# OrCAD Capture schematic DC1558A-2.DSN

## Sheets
1 Sequencer: size Custom; title: 8 - OUTPUT REGULATOR WITH SEQUENCING AND I   C; rev: 2; note: DEMO CIRCUIT 1558A
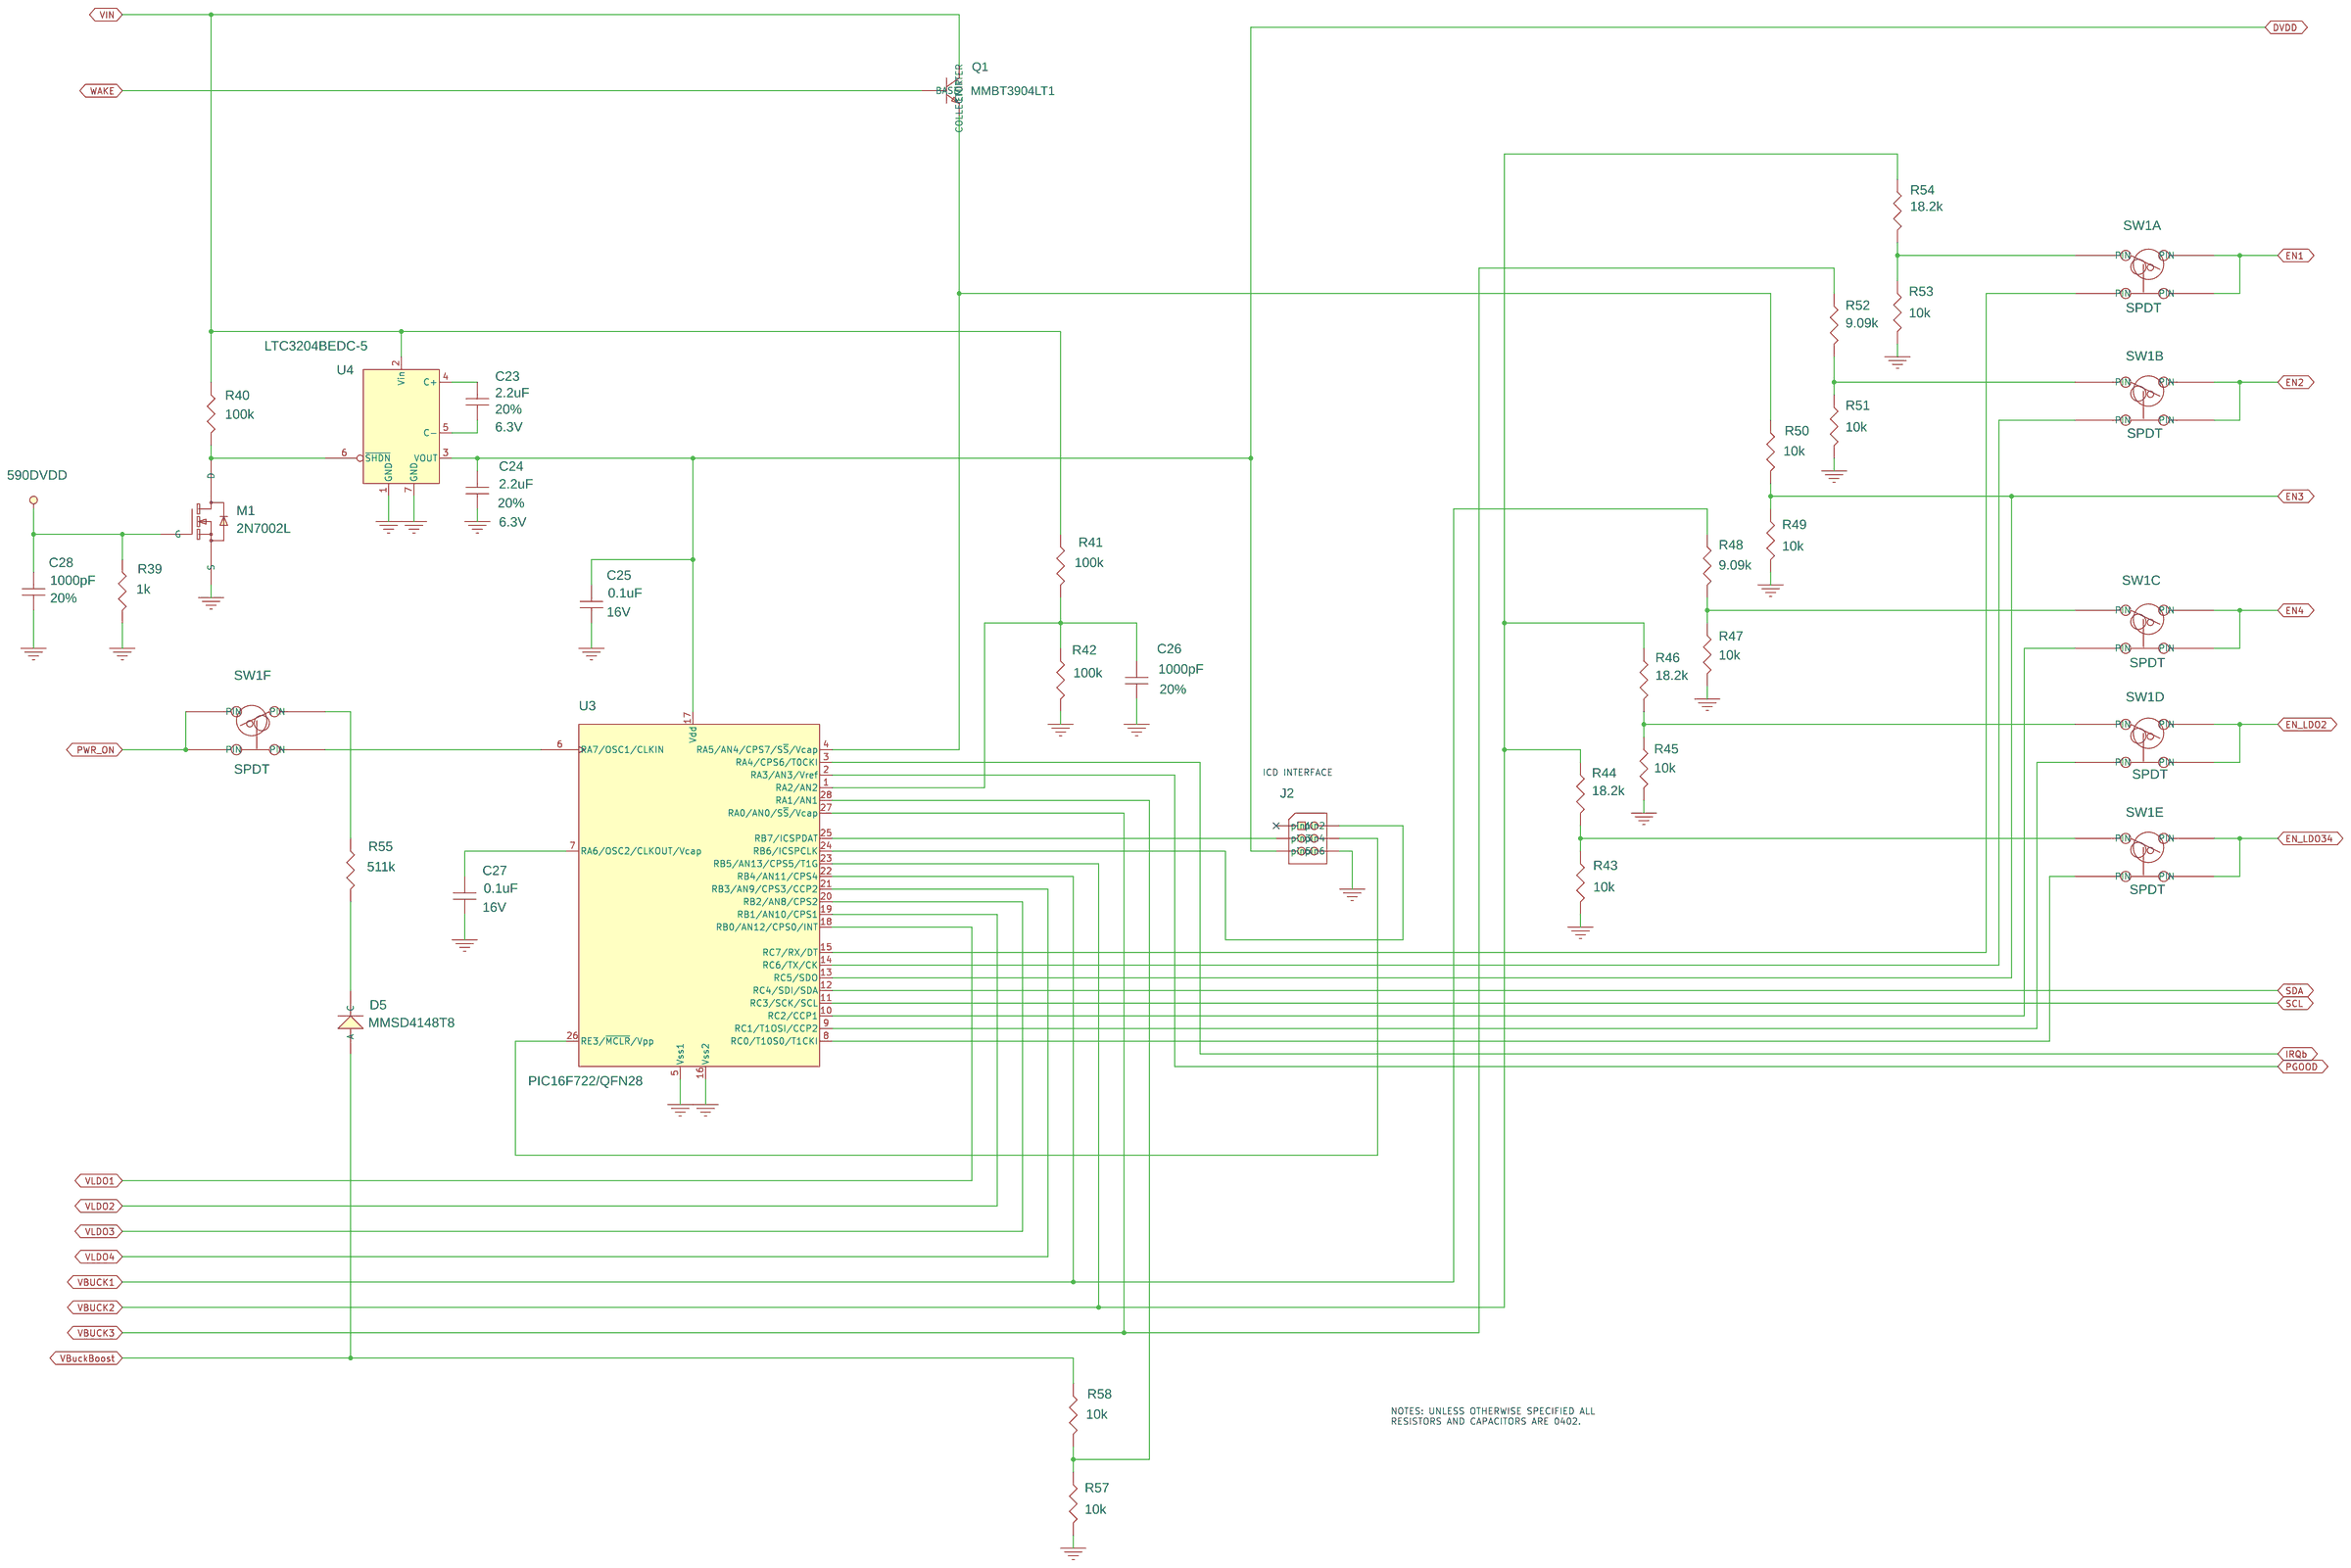
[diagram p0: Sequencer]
2 LTC3589EUJ: size Custom
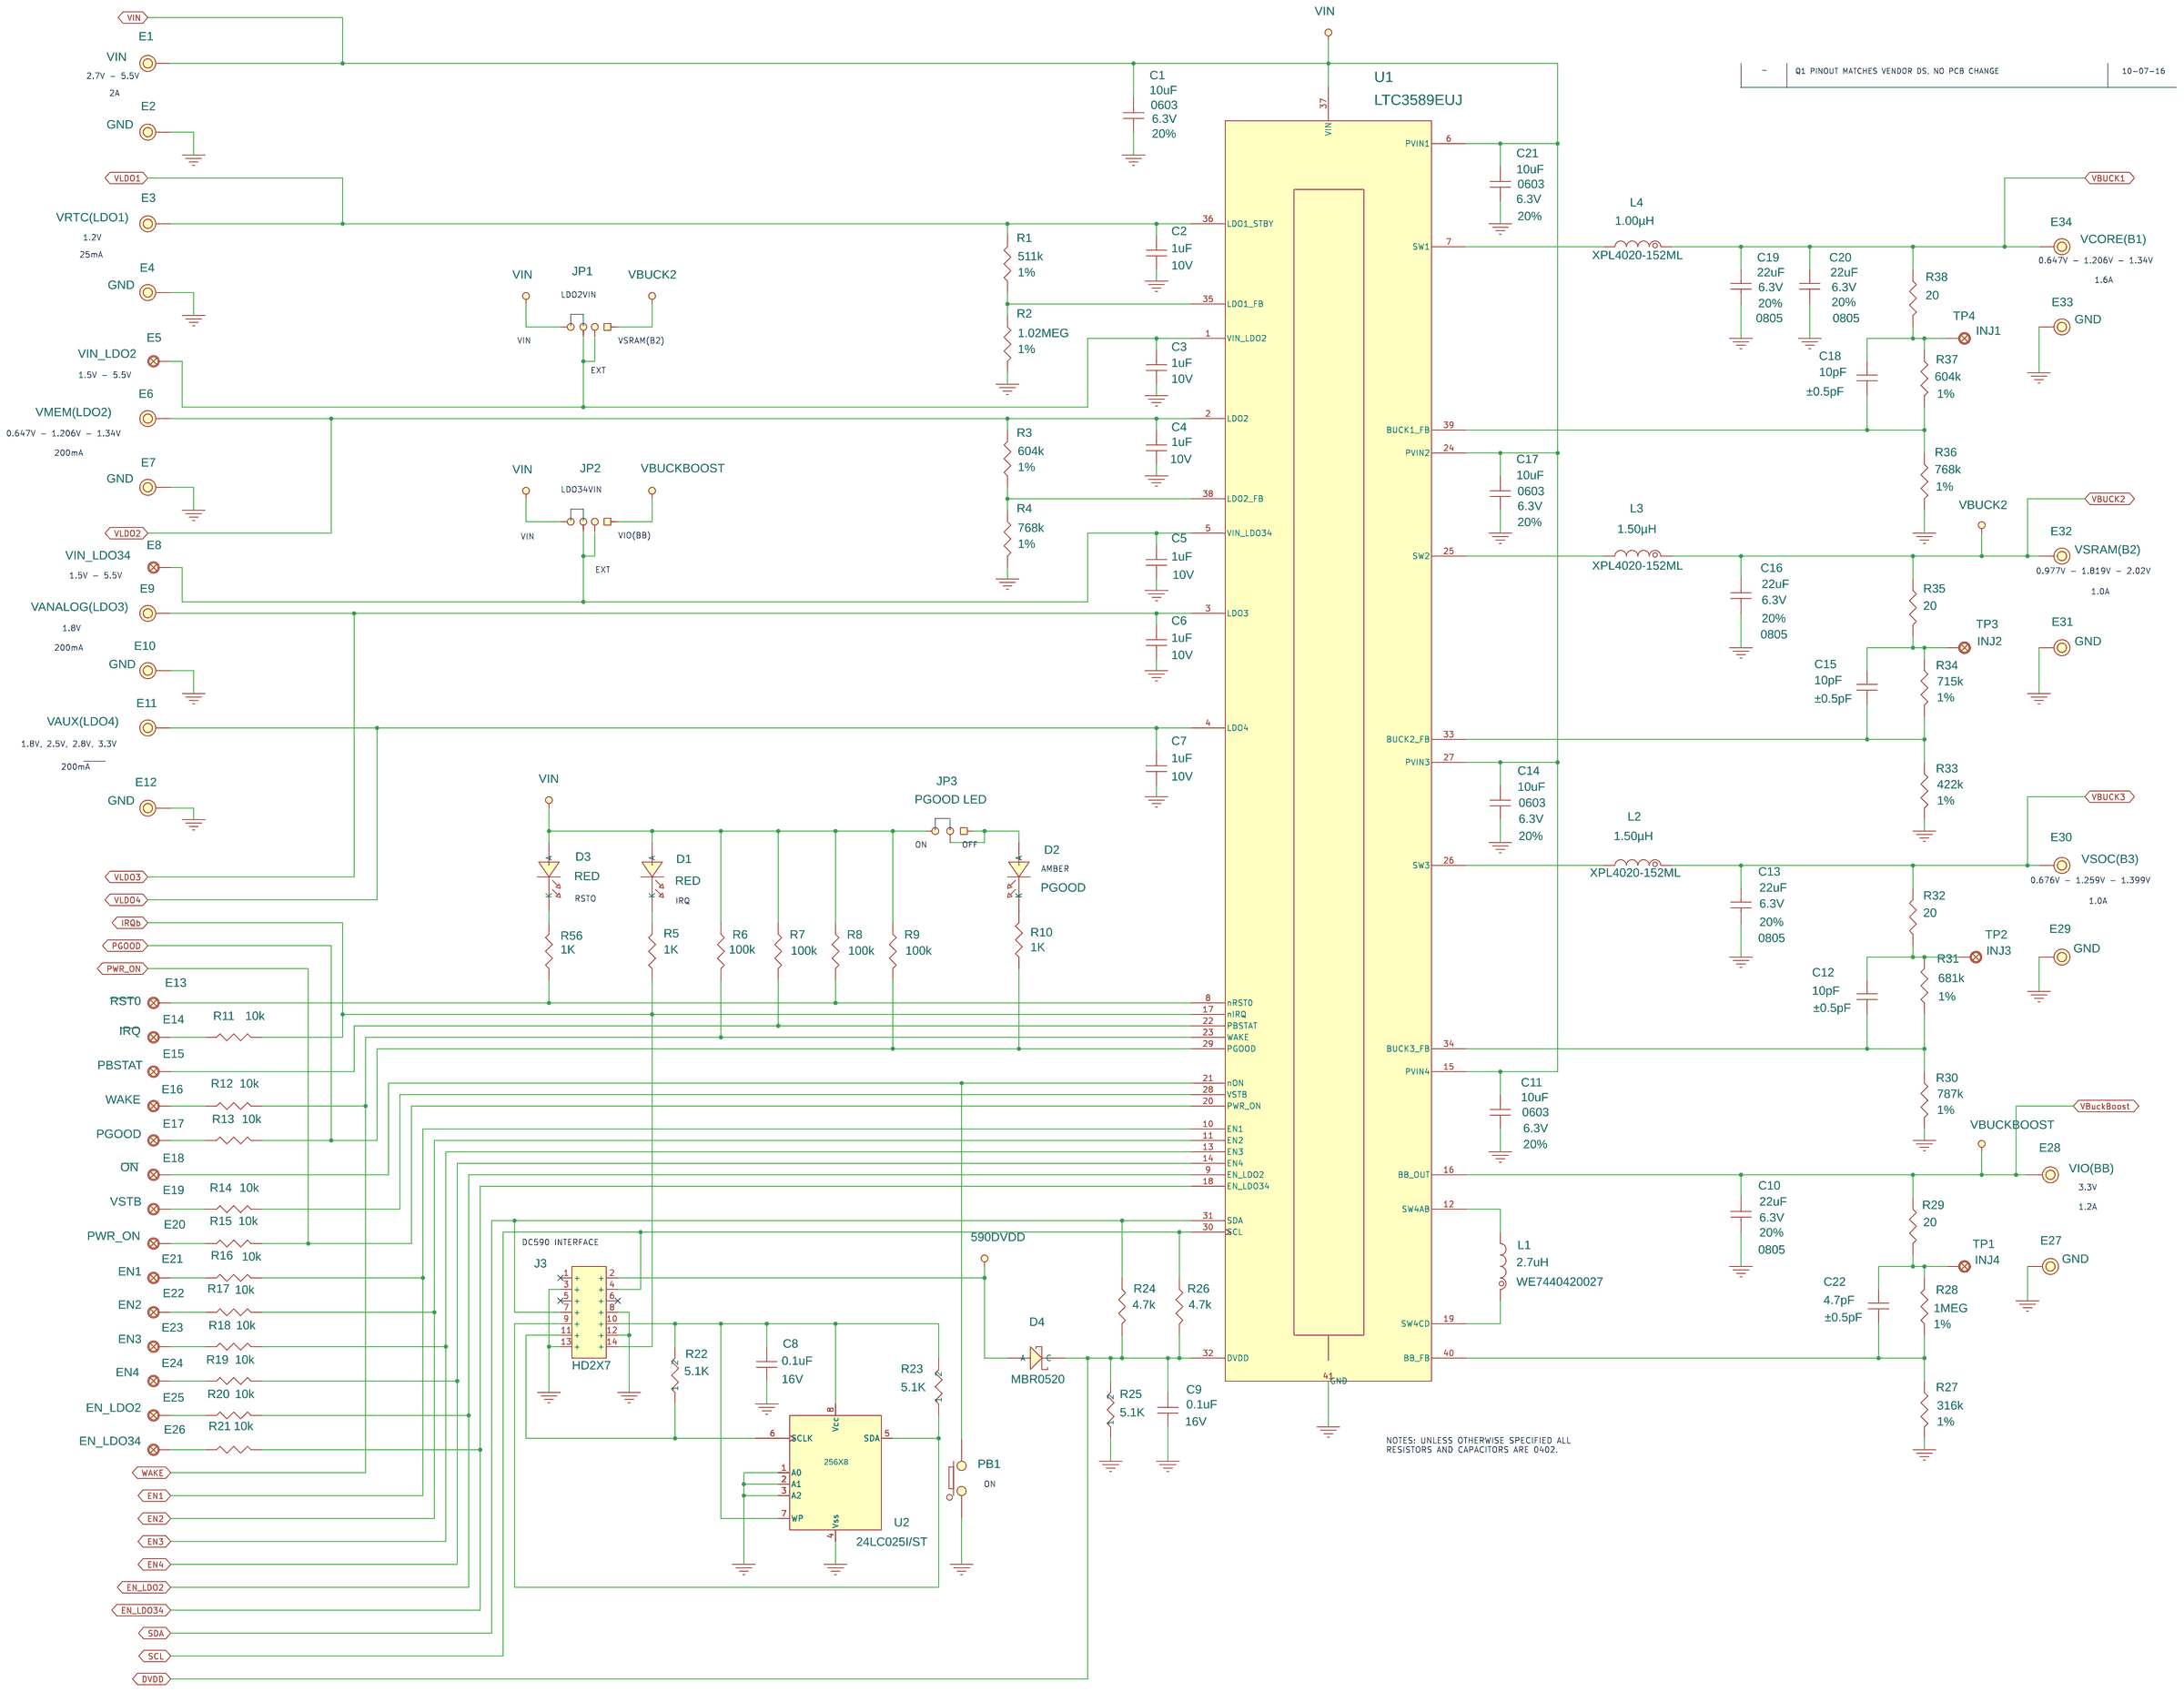
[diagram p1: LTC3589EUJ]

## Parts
sheet LTC3589EUJ
C1  10uF  [CC0603SMALL]
C2  1uF  [0402-SMALL]
C3  1uF  [0402-SMALL]
C4  1uF  [0402-SMALL]
C5  1uF  [0402-SMALL]
C6  1uF  [0402-SMALL]
C7  1uF  [0402-SMALL]
C8  0.1uF  [0402-SMALL]
C9  0.1uF  [0402-SMALL]
C10  22uF  [0805]
C11  10uF  [CC0603SMALL]
C12  10pF  [0402-SMALL]
C13  22uF  [0805]
C14  10uF  [CC0603SMALL]
C15  10pF  [0402-SMALL]
C16  22uF  [0805]
C17  10uF  [CC0603SMALL]
C18  10pF  [0402-SMALL]
C19  22uF  [0805]
C20  22uF  [0805]
C21  10uF  [CC0603SMALL]
C22  4.7pF  [0402-SMALL]
D1  RED  [LNJ208R8ARA-RED-LED]
D2  PGOOD  [LITE-ON-GREEN-LED]
D3  RED  [LNJ208R8ARA-RED-LED]
D4  MBR0520  [SOD-123]
E1  0.09"  [MILL-MAX-2501-2]
E2  0.09"  [MILL-MAX-2501-2]
E3  0.09"  [MILL-MAX-2501-2]
E4  0.09"  [MILL-MAX-2501-2]
E5  0.061"  [MILL-MAX-2308]
E6  0.09"  [MILL-MAX-2501-2]
E7  0.09"  [MILL-MAX-2501-2]
E8  0.061"  [MILL-MAX-2308]
E9  0.09"  [MILL-MAX-2501-2]
E10  0.09"  [MILL-MAX-2501-2]
E11  0.09"  [MILL-MAX-2501-2]
E12  0.09"  [MILL-MAX-2501-2]
E13  0.061"  [MILL-MAX-2308]
E14  0.061"  [MILL-MAX-2308]
E15  0.061"  [MILL-MAX-2308]
E16  0.061"  [MILL-MAX-2308]
E17  0.061"  [MILL-MAX-2308]
E18  0.061"  [MILL-MAX-2308]
E19  0.061"  [MILL-MAX-2308]
E20  0.061"  [MILL-MAX-2308]
E21  0.061"  [MILL-MAX-2308]
E22  0.061"  [MILL-MAX-2308]
E23  0.061"  [MILL-MAX-2308]
E24  0.061"  [MILL-MAX-2308]
E25  0.061"  [MILL-MAX-2308]
E26  0.061"  [MILL-MAX-2308]
E27  0.09"  [MILL-MAX-2501-2]
E28  0.09"  [MILL-MAX-2501-2]
E29  0.09"  [MILL-MAX-2501-2]
E30  0.09"  [MILL-MAX-2501-2]
E31  0.09"  [MILL-MAX-2501-2]
E32  0.09"  [MILL-MAX-2501-2]
E33  0.09"  [MILL-MAX-2501-2]
E34  0.09"  [MILL-MAX-2501-2]
J3  HD2X7  [HD2X7-079-MOLEX]
JP1  4 pin jumper  [2MMJUMP4]
JP2  4 pin jumper  [2MMJUMP4]
JP3  PGOOD LED  [2MMJUMP3]
L1  2.7uH  [IND-WE-7440420027]
L2  1.50µH  [IND-XPL4020]
L3  1.50µH  [IND-XPL4020]
L4  1.00µH  [IND-XPL4020]
PB1  EVQPPFA25  [SW-EVQPJS]
R1  511k  [0402-SMALL]
R2  1.02MEG  [0402-SMALL]
R3  604k  [0402-SMALL]
R4  768k  [0402-SMALL]
R5  1K  [0402-SMALL]
R6  100k  [0402-SMALL]
R7  100k  [0402-SMALL]
R8  100k  [0402-SMALL]
R9  100k  [0402-SMALL]
R10  1K  [0402-SMALL]
R11  10k  [0402-SMALL]
R12  10k  [0402-SMALL]
R13  10k  [0402-SMALL]
R14  10k  [0402-SMALL]
R15  10k  [0402-SMALL]
R16  10k  [0402-SMALL]
R17  10k  [0402-SMALL]
R18  10k  [0402-SMALL]
R19  10k  [0402-SMALL]
R20  10k  [0402-SMALL]
R21  10k  [0402-SMALL]
R22  5.1K  [0402-SMALL]
R23  5.1K  [0402-SMALL]
R24  4.7k  [0402-SMALL]
R25  5.1K  [0402-SMALL]
R26  4.7k  [0402-SMALL]
R27  316k  [0402-SMALL]
R28  1MEG  [0402-SMALL]
R29  20  [0402-SMALL]
R30  787k  [0402-SMALL]
R31  681k  [0402-SMALL]
R32  20  [0402-SMALL]
R33  422k  [0402-SMALL]
R34  715k  [0402-SMALL]
R35  20  [0402-SMALL]
R36  768k  [0402-SMALL]
R37  604k  [0402-SMALL]
R38  20  [0402-SMALL]
R56  1K  [0402-SMALL]
TP1  0.030"  [PAD70-70]
TP2  0.030"  [PAD70-70]
TP3  0.030"  [PAD70-70]
TP4  0.030"  [PAD70-70]
U1  LTC3589  [QFN(40)(UJ)6MMX6MM.5]
U2  24LC025I/ST  [TSSOP8]
sheet Sequencer
C23  2.2uF  [0402-SMALL]
C24  2.2uF  [0402-SMALL]
C25  0.1uF  [0402-SMALL]
C26  1000pF  [0402-SMALL]
C27  0.1uF  [0402-SMALL]
C28  1000pF  [0402-SMALL]
D5  MMSD4148T8  [SOD-123]
J2  TMM-103-02-L-D  [JP2X3/079]
M1  2N7002L  [SUPER_SOT3]
Q1  MMBT3904LT1  [MMBT3904-SOT-23]
R39  1k  [0402-SMALL]
R40  100k  [0402-SMALL]
R41  100k  [0402-SMALL]
R42  100k  [0402-SMALL]
R43  10k  [0402-SMALL]
R44  18.2k  [0402-SMALL]
R45  10k  [0402-SMALL]
R46  18.2k  [0402-SMALL]
R47  10k  [0402-SMALL]
R48  9.09k  [0402-SMALL]
R49  10k  [0402-SMALL]
R50  10k  [0402-SMALL]
R51  10k  [0402-SMALL]
R52  9.09k  [0402-SMALL]
R53  10k  [0402-SMALL]
R54  18.2k  [0402-SMALL]
R55  511k  [0402-SMALL]
R57  10k  [0402-SMALL]
R58  10k  [0402-SMALL]
SW1  SPDT  [SPDT-204-126]  (sections A,B,C,D,E,F)
U3  PIC16F722/QFN28  [6mmx6mmQFN28]
U4  LTC3204BEDC-5  [DFN(06)2MMX2MM]

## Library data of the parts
C1 C11 C14 C17 C21 = C1608X5R0J475M: 1st Part Field: 6.3V; 2nd Part Field: 0603; 3rd Part Field: CHIP,; 4th Part Field: MUR; 5th Part Field: C1608X5R0J106M; 7th Part Field: CAP, X5R; Critical: T; Layer: T; MPN: C1608X5R0J106M; Manufacturer: TDK; Populate: T; Size: 0603; Tempco: X5R; Tolerance: 20%; Voltage: 6.3V
C2-C7 = C2012X5R0J156M: 1st Part Field: 10V; 2nd Part Field: 0402; 3rd Part Field: CHIP, X5R; 5th Part Field: C1005X5R1A105K; 7th Part Field: CAP,; Critical: T; Layer: T; MPN: C1005X5R0J105KT; Manufacturer: TDK; Part Number: TDK, 1005X5R0J105M; Populate: T; Size: 0402; Tempco: X5R; Tolerance: 10%; Voltage: 10V
C8 C9 = C1608X5R0J475M: 1st Part Field: 16V; 2nd Part Field: 0402; 3rd Part Field: CHIP, X5R; 4th Part Field: MUR; 5th Part Field: GRM188R60J106ME47; 7th Part Field: CAP, X5R; Critical: T; Layer: T; MPN: GRM155R71C104KA88; Manufacturer: MUR; Populate: T; Size: 0402; Tempco: JIS-B; Tolerance: 10%; Voltage: 16V
C10 C13 C16 C19 C20 = C2012X5R0J156M: 3rd Part Field: CHIP, X5R; 4th Part Field: Taiyo-Yuden; 5th Part Field: JMK212BJ226MG; 7th Part Field: CAP,; Critical: T; Layer: T; MPN: JMK212BJ226MG; Manufacturer: Taiyo-Yuden; Part Number: Taiyo-Yuden, JMK212BJ226MG; Populate: T; Tempco: X5R; Tolerance: 20%; Voltage: 6.3V
C12 C22 = C2012X5R0J156M: 1st Part Field: 50V; 2nd Part Field: 0402; 3rd Part Field: CHIP; 4th Part Field: VISHAY; 5th Part Field: VJ0402A100DXAA; 7th Part Field: CAP,; Critical: T; Layer: T; MPN: 04025A100KAT; Manufacturer: AVX; Part Number: AVX, 04015A100KAT; Populate: T; Size: 0402; Tempco: C0G; Tolerance: ±0.5pF; Voltage: 50V
C15 C18 = C2012X5R0J156M: 1st Part Field: 50V; 2nd Part Field: 0402; 3rd Part Field: CHIP; 4th Part Field: VISHAY; 5th Part Field: VJ0402A100DXAA; 7th Part Field: CAP,; Critical: T; Layer: T; MPN: VJ0402A100DXAA; Manufacturer: VISHAY; Part Number: VISHAY, VJ0402A100DXAA; Populate: T; Size: 0402; Tempco: C0G; Tolerance: ±0.5pF; Voltage: 50V
D1 D3 = ln1351-c-tr_1: 5th Part Field: LNJ208R8ARA; 9th Part Field: SMT, GREEN; Critical: F; Irms: 1mA; Layer: T; MPN: LNJ208R8ARA; Manufacturer: PANASONIC; Part Number: LNJ208R8ARA; Populate: T; Size: 0603
D2 = ln1351-c-tr_1: 5th Part Field: LNJ336W83RA; 9th Part Field: SMT, GREEN; Part Number: LNJ336W83RA
D4 = DIODE_SCHOTTKY
E1 = E_3: TURRET; Critical: F; MPN: 2501-2; Manufacturer: MIL; Populate: T; Signal: VIN; Size: 0.09
E2 E4 E7 E10 E12 E27 E29 E31 E33 = E_3: TURRET; Critical: F; MPN: 2501-2; Manufacturer: MIL; Populate: T; Signal: GND; Size: 0.09
E3 = E_3: TURRET; Critical: F; MPN: 2501-2; Manufacturer: MIL; Populate: T; Signal: VRTC(LDO1); Size: 0.09
E5 = TP_KEY_1502-2_0: 4th Part Field: MILL-MAX; 5th Part Field: 2308-2; 7th Part Field: TURRET, SIGNAL; 9th Part Field: NTC; Critical: F; MPN: 2308-2; Manufacturer: MIL; Part Number: MILL-MAX 2308-2; Populate: T; Signal: VIN_LDO2; Size: 0.061
E6 = E_3: TURRET; Critical: F; MPN: 2501-2; Manufacturer: MIL; Populate: T; Signal: VMEM(LDO2); Size: 0.09
E8 = TP_KEY_1502-2_0: 4th Part Field: MILL-MAX; 5th Part Field: 2308-2; 7th Part Field: TURRET, SIGNAL; 9th Part Field: NTC; Critical: F; MPN: 2308-2; Manufacturer: MIL; Part Number: MILL-MAX 2308-2; Populate: T; Signal: VIN_LDO34; Size: 0.061
E9 = E_3: TURRET; Critical: F; MPN: 2501-2; Manufacturer: MIL; Populate: T; Signal: VANALOG(LDO3); Size: 0.09
E11 = E_3: TURRET; Critical: F; MPN: 2501-2; Manufacturer: MIL; Populate: T; Signal: VAUX(LDO4); Size: 0.09
E13 = TP_KEY_1502-2_0: 4th Part Field: MILL-MAX; 5th Part Field: 2308-2; 7th Part Field: TURRET, SIGNAL; 9th Part Field: NTC; Critical: F; MPN: 2308-2; Manufacturer: MIL; Part Number: MILL-MAX 2308-2; Populate: T; Signal: RST0; Size: 0.061
E14 = TP_KEY_1502-2_0: 4th Part Field: MILL-MAX; 5th Part Field: 2308-2; 7th Part Field: TURRET, SIGNAL; 9th Part Field: NTC; Critical: F; MPN: 2308-2; Manufacturer: MIL; Part Number: MILL-MAX 2308-2; Populate: T; Signal: IRQ; Size: 0.061
E15 = TP_KEY_1502-2_0: 4th Part Field: MILL-MAX; 5th Part Field: 2308-2; 7th Part Field: TURRET, SIGNAL; 9th Part Field: NTC; Critical: F; MPN: 2308-2; Manufacturer: MIL; Part Number: MILL-MAX 2308-2; Populate: T; Signal: PBSTAT; Size: 0.061
E16 = TP_KEY_1502-2_0: 4th Part Field: MILL-MAX; 5th Part Field: 2308-2; 7th Part Field: TURRET, SIGNAL; 9th Part Field: NTC; Critical: F; MPN: 2308-2; Manufacturer: MIL; Part Number: MILL-MAX 2308-2; Populate: T; Signal: WAKE; Size: 0.061
E17 = TP_KEY_1502-2_0: 4th Part Field: MILL-MAX; 5th Part Field: 2308-2; 7th Part Field: TURRET, SIGNAL; 9th Part Field: NTC; Critical: F; MPN: 2308-2; Manufacturer: MIL; Part Number: MILL-MAX 2308-2; Populate: T; Signal: PGOOD; Size: 0.061
E18 = TP_KEY_1502-2_0: 4th Part Field: MILL-MAX; 5th Part Field: 2308-2; 7th Part Field: TURRET, SIGNAL; 9th Part Field: NTC; Critical: F; MPN: 2308-2; Manufacturer: MIL; Part Number: MILL-MAX 2308-2; Populate: T; Signal: ON; Size: 0.061
E19 = TP_KEY_1502-2_0: 4th Part Field: MILL-MAX; 5th Part Field: 2308-2; 7th Part Field: TURRET, SIGNAL; 9th Part Field: NTC; Critical: F; MPN: 2308-2; Manufacturer: MIL; Part Number: MILL-MAX 2308-2; Populate: T; Signal: VSTB; Size: 0.061
E20 = TP_KEY_1502-2_0: 4th Part Field: MILL-MAX; 5th Part Field: 2308-2; 7th Part Field: TURRET, SIGNAL; 9th Part Field: NTC; Critical: F; MPN: 2308-2; Manufacturer: MIL; Part Number: MILL-MAX 2308-2; Populate: T; Signal: PWR_ON; Size: 0.061
E21 = TP_KEY_1502-2_0: 4th Part Field: MILL-MAX; 5th Part Field: 2308-2; 7th Part Field: TURRET, SIGNAL; 9th Part Field: NTC; Critical: F; MPN: 2308-2; Manufacturer: MIL; Part Number: MILL-MAX 2308-2; Populate: T; Signal: EN1; Size: 0.061
E22 = TP_KEY_1502-2_0: 4th Part Field: MILL-MAX; 5th Part Field: 2308-2; 7th Part Field: TURRET, SIGNAL; 9th Part Field: NTC; Critical: F; MPN: 2308-2; Manufacturer: MIL; Part Number: MILL-MAX 2308-2; Populate: T; Signal: EN2; Size: 0.061
E23 = TP_KEY_1502-2_0: 4th Part Field: MILL-MAX; 5th Part Field: 2308-2; 7th Part Field: TURRET, SIGNAL; 9th Part Field: NTC; Critical: F; MPN: 2308-2; Manufacturer: MIL; Part Number: MILL-MAX 2308-2; Populate: T; Signal: EN3; Size: 0.061
E24 = TP_KEY_1502-2_0: 4th Part Field: MILL-MAX; 5th Part Field: 2308-2; 7th Part Field: TURRET, SIGNAL; 9th Part Field: NTC; Critical: F; MPN: 2308-2; Manufacturer: MIL; Part Number: MILL-MAX 2308-2; Populate: T; Signal: EN4; Size: 0.061
E25 = TP_KEY_1502-2_0: 4th Part Field: MILL-MAX; 5th Part Field: 2308-2; 7th Part Field: TURRET, SIGNAL; 9th Part Field: NTC; Critical: F; MPN: 2308-2; Manufacturer: MIL; Part Number: MILL-MAX 2308-2; Populate: T; Signal: EN_LDO2; Size: 0.061
E26 = TP_KEY_1502-2_0: 4th Part Field: MILL-MAX; 5th Part Field: 2308-2; 7th Part Field: TURRET, SIGNAL; 9th Part Field: NTC; Critical: F; MPN: 2308-2; Manufacturer: MIL; Part Number: MILL-MAX 2308-2; Populate: T; Signal: EN_LDO34; Size: 0.061
E28 = E_3: TURRET; Critical: F; MPN: 2501-2; Manufacturer: MIL; Populate: T; Signal: VIO(BB); Size: 0.09
E30 = E_3: TURRET; Critical: F; MPN: 2501-2; Manufacturer: MIL; Populate: T; Signal: VSOC(B3); Size: 0.09
E32 = E_3: TURRET; Critical: F; MPN: 2501-2; Manufacturer: MIL; Populate: T; Signal: VSRAM(B2); Size: 0.09
E34 = E_3: TURRET; Critical: F; MPN: 2501-2; Manufacturer: MIL; Populate: T; Signal: VCORE(B1); Size: 0.09
J3 = CON14AP: 3rd Part Field: 2x7 2MM STRAIGHT; 4th Part Field: MOLEX/WALDEN; 5th Part Field: 87831-1412; 7th Part Field: Socket; Critical: F; MPN: 87831-1420; Manufacturer: MOL; Populate: T; Size: 2X7
JP1 JP2 = 2MMX2MM4PIN_1: Critical: F; MPN: TMM-104-02-L-S; Manufacturer: SAM; Populate: T; Size: 2mm
JP3 = JP3X1_079_NO_6: 4TH PART FIELD: SAMTEC; 5TH PART FIELD: TMM-103-02-L-S; 7TH PART FIELD: HEADER; Part Number: TMM-103-02-L-S
L1 = MSS5131-222MLC: 5th Part Field: WE7440420027
L2 L3 = XPL4020-152MLC_0: PART: XPL4020-152ML
L4 = XPL4020-102MLC: PART: XPL4020-152ML
PB1 = SW-BUTTON_0: 4th Part Field: Panasonic; 7th Part Field: SW MC
R1 = CR16-103JM_0: 1st Part Field: 1/16W; 2nd Part Field: 0402; 3rd Part Field: CHIP; 4th Part Field: VISHAY; 5th Part Field: CRCW0402511KFKED; 7th Part Field: RES,; Critical: T; Layer: T; MPN: CRCW0402511KFKED; Manufacturer: VIS; Part Number: VISHAY CRCW0402 511k 1%; Populate: T; Size: 0402; Tempco: 200PPM; Tolerance: 1%; Voltage: 50V; Wattage: 1/16W
R2 R4 R28 R30 R33 R36 = CR16-103JM_0: 1st Part Field: 1/16W; 2nd Part Field: 0402; 3rd Part Field: CHIP; 4th Part Field: VISHAY; 5th Part Field: CRCW04021M00FKED; 7th Part Field: RES,; Critical: T; Layer: T; MPN: CRCW04021M00FKED; Manufacturer: VIS; Part Number: VISHAY CRCW0402 1MEG 1%; Populate: T; Size: 0402; Tempco: 200PPM; Tolerance: 1%; Voltage: 50V; Wattage: 1/16W
R3 R37 = CR16-103JM_0: 1st Part Field: 1/16W; 2nd Part Field: 0402; 3rd Part Field: CHIP; 4th Part Field: VISHAY; 5th Part Field: CRCW0402787KFKED; 7th Part Field: RES,; Critical: T; Layer: T; MPN: CRCW0402787KFKED; Manufacturer: VIS; Part Number: VISHAY CRCW0402 787k 1%; Populate: T; Size: 0402; Tempco: 200PPM; Tolerance: 1%; Voltage: 50V; Wattage: 1/16W
R5 R56 = CR16-103JM_0: 1st Part Field: 1/16W; 2nd Part Field: 0402; 3rd Part Field: CHIP; 4th Part Field: VISHAY; 5th Part Field: CRCW04021K00JNED; 7th Part Field: RES; Part Number: VISHAY CRCW04021K00JNED; Tolerance: 5%
R6-R9 R11-R21 = CR16-103JM_0: 1st Part Field: 1/16W; 2nd Part Field: 0402; 3rd Part Field: CHIP; 4th Part Field: VISHAY; 5th Part Field: CRCW0402100KJNED; 7th Part Field: RES,; Critical: T; Layer: T; MPN: CRCW04027153F; Manufacturer: VIS; Part Number: VISHAY CRCW0402100KJNED; Populate: T; Size: 0402; Tempco: 200PPM; Tolerance: 5%; Voltage: 50V; Wattage: 1/16W
R10 = CR16-103JM_0: 1st Part Field: 1/16W; 3rd Part Field: CHIP; 4th Part Field: VISHAY; 5th Part Field: CRCW04021K00JNED; 7th Part Field: RES; Part Number: VISHAY CRCW04021K00JNED; Tolerance: 5%
R22 = RESISTOR: 1st Part Field: 1/16W; 2nd Part Field: 0402; 3rd Part Field: CHIP; 4th Part Field: VISHAY; 5th Part Field: CRCW04025K10JNED; 7th Part Field: RES,; Critical: F; Layer: T; MPN: CRCW04025K10JNED; Manufacturer: VIS; Part Number: VISHAY, CRCW04025K10JNED; Populate: T; Size: 0402; Tempco: 200PPM; Tolerance: 5%; Voltage: 30V; Wattage: 1/16W
R23 = RESISTOR_1: 1st Part Field: 0.1W; 2nd Part Field: 0402; 3rd Part Field: CHIP; 4th Part Field: VISHAY; 5th Part Field: CRCW04025101J; 7th Part Field: RES,; Critical: F; Layer: T; MPN: CRCW04025101J; Manufacturer: VIS; Part Number: PHILLIPS, 9C12063A51R0JM; Populate: T; Size: 0402; Tempco: 200PPM; Tolerance: 5%; Voltage: 50V; Wattage: 1/16W
R24 R26 = CRCW04021K00FKED: 5th Part Field: CRCW04024K70JNED; Layer: B; Tolerance: 5%
R25 = RESISTOR_2: 1st Part Field: 0.1W; 2nd Part Field: 0402; 3rd Part Field: CHIP; 4th Part Field: VISHAY; 5th Part Field: CRCW04025101J; 7th Part Field: RES,; Critical: F; Layer: T; MPN: CRCW04025101J; Manufacturer: VIS; Part Number: PHILLIPS, 9C12063A51R0JM; Populate: T; Size: 0402; Tempco: 200PPM; Tolerance: 5%; Voltage: 50V; Wattage: 1/16W
R27 = CR16-103JM_0: 1st Part Field: 1/16W; 2nd Part Field: 0402; 3rd Part Field: CHIP; 4th Part Field: VISHAY; 5th Part Field: CRCW0402316KFKED; 7th Part Field: RES,; Critical: T; Layer: T; MPN: CRCW0402316KFKED; Manufacturer: VIS; Part Number: VISHAY CRCW0402 316k 1%; Populate: T; Size: 0402; Tempco: 200PPM; Tolerance: 1%; Voltage: 50V; Wattage: 1/16W
R29 R32 R35 = CR16-103JM_0: 1st Part Field: 0.1W; 2nd Part Field: 0402; 3rd Part Field: CHIP; 4th Part Field: VISHAY; 5th Part Field: CRCW040220RJ; 7th Part Field: RES,; Critical: T; Layer: B; MPN: CRCW040220RJ; Manufacturer: VIS; Part Number: VISHAY CRCW0402 806K 1%; Populate: T; Size: 0402; Tempco: 200PPM; Tolerance: 5%; Voltage: 50V; Wattage: 1/16W
R31 = CR16-103JM_0: 1st Part Field: 1/16W; 2nd Part Field: 0402; 3rd Part Field: CHIP; 4th Part Field: VISHAY; 5th Part Field: CRCW0402866KFKED; 7th Part Field: RES,; Critical: T; Layer: T; MPN: CRCW0402866KFKED; Manufacturer: VIS; Part Number: VISHAY CRCW0402 866K 1%; Populate: T; Size: 0402; Tempco: 200PPM; Tolerance: 1%; Voltage: 50V; Wattage: 1/16W
R34 = CR16-103JM_0: 1st Part Field: 1/16W; 2nd Part Field: 0402; 3rd Part Field: CHIP; 4th Part Field: VISHAY; 5th Part Field: CRCW04021M69FKED; 7th Part Field: RES,; Critical: T; Layer: T; MPN: CRCW04021M69FKED; Manufacturer: VIS; Part Number: VISHAY CRCW0402 1.69MEG 1%; Populate: T; Size: 0402; Tempco: 200PPM; Tolerance: 1%; Voltage: 50V; Wattage: 1/16W
R38 = CRCW040220R0JNED
TP1 = TP_KEY_1502-2_3: Layer: B; Signal: INJ4
TP2 = TP_KEY_1502-2_3: Layer: B; Signal: INJ3
TP3 = TP_KEY_1502-2_3: Layer: B; Signal: INJ2
TP4 = TP_KEY_1502-2_3: Layer: B; Signal: INJ1
U1 = LTC4089edjc_180: 5th Part Field: LTC3589EUJ; 7th Part Field: IC,; Critical: T; Layer: T; MPN: LTC3556EUJ; Manufacturer: LTC; Part Number: LTC3555EUJ; Populate: T
U2 = LT1762_2: 256X8; 4th Part Field: MICROCHIP; 5th Part Field: 24LC025-I/ST; 7th Part Field: IC,; Critical: F; Layer: T; MPN: 24LC025-I/ST; Manufacturer: MIC; Part Number: MICROCHIP, 24LC025-I/ST; Populate: T
C23 C24 = C2012X5R0J156M: 1st Part Field: 10V; 2nd Part Field: 0402; 3rd Part Field: CHIP, X5R; 5th Part Field: C1005X5R1A105K; 7th Part Field: CAP,; Critical: T; Layer: T; MPN: C1005X5R0J105KT; Manufacturer: TDK; Part Number: TDK, 1005X5R0J105M; Populate: T; Size: 0402; Tempco: X5R; Tolerance: 20%; Voltage: 6.3V
C25 C27 = C1608X5R0J475M: 1st Part Field: 16V; 2nd Part Field: 0402; 3rd Part Field: CHIP, X5R; 4th Part Field: MUR; 5th Part Field: GRM188R60J106ME47; 7th Part Field: CAP, X5R; Critical: T; Layer: B; MPN: GRM155R71C104KA88; Manufacturer: MUR; Populate: T; Size: 0402; Tempco: JIS-B; Tolerance: 10%; Voltage: 16V
C26 C28 = C1608X5R0J475M: 1st Part Field: 50V; 2nd Part Field: 0402; 3rd Part Field: CHIP, BX; 4th Part Field: VISHAY; 5th Part Field: VJ0402X103MXAA; 7th Part Field: CAP, BX; Critical: T; Layer: B; MPN: GRM155R71C104KA88; Manufacturer: MUR; Populate: T; Size: 0402; Tempco: JIS-B; Tolerance: 20%; Voltage: 50V
D5 = DIODE
J2 = 5555077-1_2: Layer: B
M1 = Si2306BDS_1: Critical: T; Irms: 2.5A; Layer: T; MPN: FDN-372S; Manufacturer: Fairchild; Populate: T; Size: SuperSOT-3; Voltage: 30V
Q1 = MMBT3904-SOT-23_0
R39 = CRCW04021K00FKED: 5th Part Field: CRCW04021K00JNED; Layer: B; Tolerance: 5%
R40-R42 = CRCW04021K00FKED: 5th Part Field: CRCW0402100KFKED; Layer: B
R43-R54 R57 R58 = CRCW04021K00FKED: Layer: B
R55 = CRCW04021K00FKED: 5th Part Field: CRCW0402511KFKED; Layer: B
SW1 = 208-126LPST_4
U3 = PIC16LF722-I_SO_0: Layer: B
U4 = LTC3204B-5_0

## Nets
DVDD: C9.2 C24.2 C25.2 D4.1(C) J2.5(pin5) R24.2(pin2) R25.2 R26.2(pin2) U1.32(DVDD) U3.17(Vdd) U4.3(VOUT)
GND: C1.1 C2.1 C3.1 C4.1 C5.1 C6.1 C7.1 C8.1 C9.1 C10.2 C11.1 C13.2 C14.1 C16.2 C17.1 C19.2 C20.2 C21.1 C24.1 C25.1 C26.1 C27.1 C28.1 E2.1(A) E4.1(A) E7.1(A) E10.1(A) E12.1(A) E27.1(A) E29.1(A) E31.1(A) E33.1(A) J2.6(pin6) J3.3(+) J3.8(+) J3.12(+) J3.13(+) M1.2(S) PB1.2 R2.1 R4.1 R25.1 R27.1 R30.1 R33.1 R36.1 R39.2(pin2) R42.2(pin2) R43.2(pin2) R45.2(pin2) R47.2(pin2) R49.2(pin2) R51.2(pin2) R53.2(pin2) R57.2(pin2) U1.41(GND) U2.1(A0) U2.2(A1) U2.3(A2) U2.4(Vss) U3.5(Vss1) U3.16(Vss2) U4.1(GND) U4.7(GND)
VIN: C1.2 C11.2 C14.2 C17.2 C21.2 D1.1(A) D3.1(A) E1.1(A) JP1.4 JP2.4 JP3.3 Q1.3(COLLECTOR) R6.2 R7.2 R8.2 R9.2 R40.1(pin1) R41.1(pin1) U1.6(PVIN1) U1.15(PVIN4) U1.24(PVIN2) U1.27(PVIN3) U1.37(VIN) U4.2(Vin)
590DVDD: C28.2 D4.2(A) J3.2(+) M1.1(G) R39.1(pin1)
EN1: R16.1 SW1.23(PIN) SW1.24(PIN) U1.10(EN1)
EN2: R17.1 SW1.21(PIN) SW1.22(PIN) U1.11(EN2)
EN3: R18.1 R49.1(pin1) R50.2(pin2) U1.13(EN3) U3.13(RC5/SDO)
EN4: R19.1 SW1.19(PIN) SW1.20(PIN) U1.14(EN4)
EN_LDO2: R20.1 SW1.17(PIN) SW1.18(PIN) U1.9(EN_LDO2)
EN_LDO34: R21.1 SW1.15(PIN) SW1.16(PIN) U1.18(EN_LDO34)
IRQb: J3.14(+) R5.2 R11.1 U1.17(nIRQ) U3.3(RA4/CPS6/T0CKI)
PGOOD: R9.1 R10.2 R13.1 U1.29(PGOOD) U3.2(RA3/AN3/Vref)
PWR_ON: R15.1 SW1.13(PIN) SW1.14(PIN) U1.20(PWR_ON)
SCL: J3.4(+) R26.1(pin1) U1.30(SCL) U3.11(RC3/SCK/SCL)
SDA: J3.7(+) R24.1(pin1) U1.31(SDA) U3.12(RC4/SDI/SDA)
VBUCK1: C19.1 C20.1 E34.1(A) L4.1 R38.1(pin1) R48.1(pin1) U3.22(RB4/AN11/CPS4)
VBUCK2: C16.1 E32.1(A) JP1.1 L3.1 R35.2 R44.1(pin1) R46.1(pin1) R54.1(pin1) U3.23(RB5/AN13/CPS5/T1G)
VBUCK3: C13.1 E30.1(A) L2.1 R32.1 R52.1(pin1) U3.27(RA0/AN0/S~{S}/Vcap)
VBuckBoost: C10.1 D5.2(A) E28.1(A) JP2.1 R29.2 R58.1(pin1) U1.16(BB_OUT)
VLDO1: C2.2 E3.1(A) R1.2 U1.36(LDO1_STBY) U3.18(RB0/AN12/CPS0/INT)
VLDO2: C4.2 E6.1(A) R3.2 U1.2(LDO2) U3.19(RB1/AN10/CPS1)
VLDO3: C6.2 E9.1(A) U1.3(LDO3) U3.20(RB2/AN8/CPS2)
VLDO4: C7.2 E11.1(A) U1.4(LDO4) U3.21(RB3/AN9/CPS3/CCP2)
WAKE: Q1.1(BASE) R6.1 R12.1 U1.23(WAKE)
N1190197: C8.2 J3.10(+) R22.2 R23.2 U2.7(WP) U2.8(Vcc)
N1202324: J3.11(+) R22.1 U2.6(SCLK)
N1204425: J3.9(+) R23.1 U2.5(SDA)
N16628252: C15.2 R33.2 R34.1 U1.33(BUCK2_FB)
N16640628: C12.2 R30.2 R31.1 U1.34(BUCK3_FB)
N16788518: D5.1(C) R55.2(pin2)
N16802037: D2.2(K) R10.1
N16808971: R57.1(pin1) R58.2(pin2) U3.28(RA1/AN1)
N16822971: C22.1 R28.2 R29.1 TP1.1
N16822979: C22.2 R27.2 R28.1 U1.40(BB_FB)
N16823128: C12.1 R31.2 R32.2 TP2.1
N16823292: C15.1 R34.2 R35.1 TP3.1
N16823563: C18.1 R37.2 R38.2(pin2) TP4.1
N16823564: C18.2 R36.2 R37.1 U1.39(BUCK1_FB)
N16828051: R55.1(pin1) SW1.11(PIN)
N16828450: SW1.12(PIN) U3.6(RA7/OSC1/CLKIN)
N17091409: R1.1 R2.2 U1.35(LDO1_FB)
N17092690: C3.2 E5.1 JP1.2 JP1.3 U1.1(VIN_LDO2)
N17092694: R3.1 R4.2 U1.38(LDO2_FB)
N17095322: C5.2 E8.1 JP2.2 JP2.3 U1.5(VIN_LDO34)
N17102813: E15.1 R7.1 U1.22(PBSTAT)
N17103563: E13.1 R8.1 R56.2 U1.8(nRST0)
N17112077: L1.1 U1.19(SW4CD)
N17119852: L2.2 U1.26(SW3)
N17119854: L3.2 U1.25(SW2)
N17119856: L4.2 U1.7(SW1)
N17125059: L1.2 U1.12(SW4AB)
N17127886: D2.1(A) JP3.1 JP3.2
N17129080: E14.1 R11.2
N17134880: E18.1 PB1.1 U1.21(nON)
N17134934: R14.1 U1.28(VSTB)
N17147561: D1.2(K) R5.1
N17166098: SW1.4(PIN) U3.14(RC6/TX/CK)
N17166134: SW1.2(PIN) U3.15(RC7/RX/DT)
N17166180: SW1.6(PIN) U3.10(RC2/CCP1)
N17166216: SW1.8(PIN) U3.9(RC1/T1OSI/CCP2)
N17166260: SW1.10(PIN) U3.8(RC0/T10S0/T1CKI)
N17166320: Q1.2(EMITTER) R50.1(pin1) U3.4(RA5/AN4/CPS7/S~{S}/Vcap)
N17169091: J2.4(pin4) U3.26(RE3/~{MCLR}/Vpp)
N17169181: J2.2(pin2) U3.24(RB6/ICSPCLK)
N17175403: R47.1(pin1) R48.2(pin2) SW1.5(PIN)
N17175407: R43.1(pin1) R44.2(pin2) SW1.9(PIN)
N17175453: R45.1(pin1) R46.2(pin2) SW1.7(PIN)
N17175523: R51.1(pin1) R52.2(pin2) SW1.3(PIN)
N17177160: R53.1(pin1) R54.2(pin2) SW1.1(PIN)
N17184956: C26.2 R41.2(pin2) R42.1(pin1) U3.1(RA2/AN2)
N17209947: C23.2 U4.4(C+)
N17209967: C23.1 U4.5(C-)
N17236404: E16.1 R12.2
N17236431: E17.1 R13.2
N17236460: E19.1 R14.2
N17236485: E20.1 R15.2
N17237248: E21.1 R16.2
N17237260: E22.1 R17.2
N17237272: E23.1 R18.2
N17237284: E24.1 R19.2
N17237296: E25.1 R20.2
N17237308: E26.1 R21.2
N17238852: M1.3(D) R40.2(pin2) U4.6(~{SHDN})
N17265250: C27.2 U3.7(RA6/OSC2/CLKOUT/Vcap)
N17266480: D3.2(K) R56.1
N17298796: J2.3(pin3) U3.25(RB7/ICSPDAT)

Not connected (* = marked no-connect by the designer): J2 1(pin1)*; J3 1(+)* 5(+)* 6(+)*

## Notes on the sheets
sheet 1
- ICD INTERFACE
- NOTES: UNLESS OTHERWISE SPECIFIED ALL
  RESISTORS AND CAPACITORS ARE 0402.
sheet 2
- 2.7V - 5.5V
- -
- Q1 PINOUT MATCHES VENDOR DS, NO PCB CHANGE
- 10-07-16
- 2A
- 1.2V
- 25mA
- 0.647V - 1.206V - 1.34V
- 1.6A
- LDO2VIN
- VIN
- VSRAM(B2)
- 1.5V - 5.5V
- EXT
- 0.647V - 1.206V - 1.34V
- 200mA
- LDO34VIN
- VIN
- VIO(BB)
- 1.5V - 5.5V
- EXT
- 0.977V - 1.819V - 2.02V
- 1.0A
- 1.8V
- 200mA
- 1.8V, 2.5V, 2.8V, 3.3V
- 200mA
- ON
- OFF
- AMBER
- 0.676V - 1.259V - 1.399V
- RSTO
- IRQ
- 1.0A
- 3.3V
- 1.2A
- DC590 INTERFACE
- NOTES: UNLESS OTHERWISE SPECIFIED ALL
  RESISTORS AND CAPACITORS ARE 0402.
- ON
